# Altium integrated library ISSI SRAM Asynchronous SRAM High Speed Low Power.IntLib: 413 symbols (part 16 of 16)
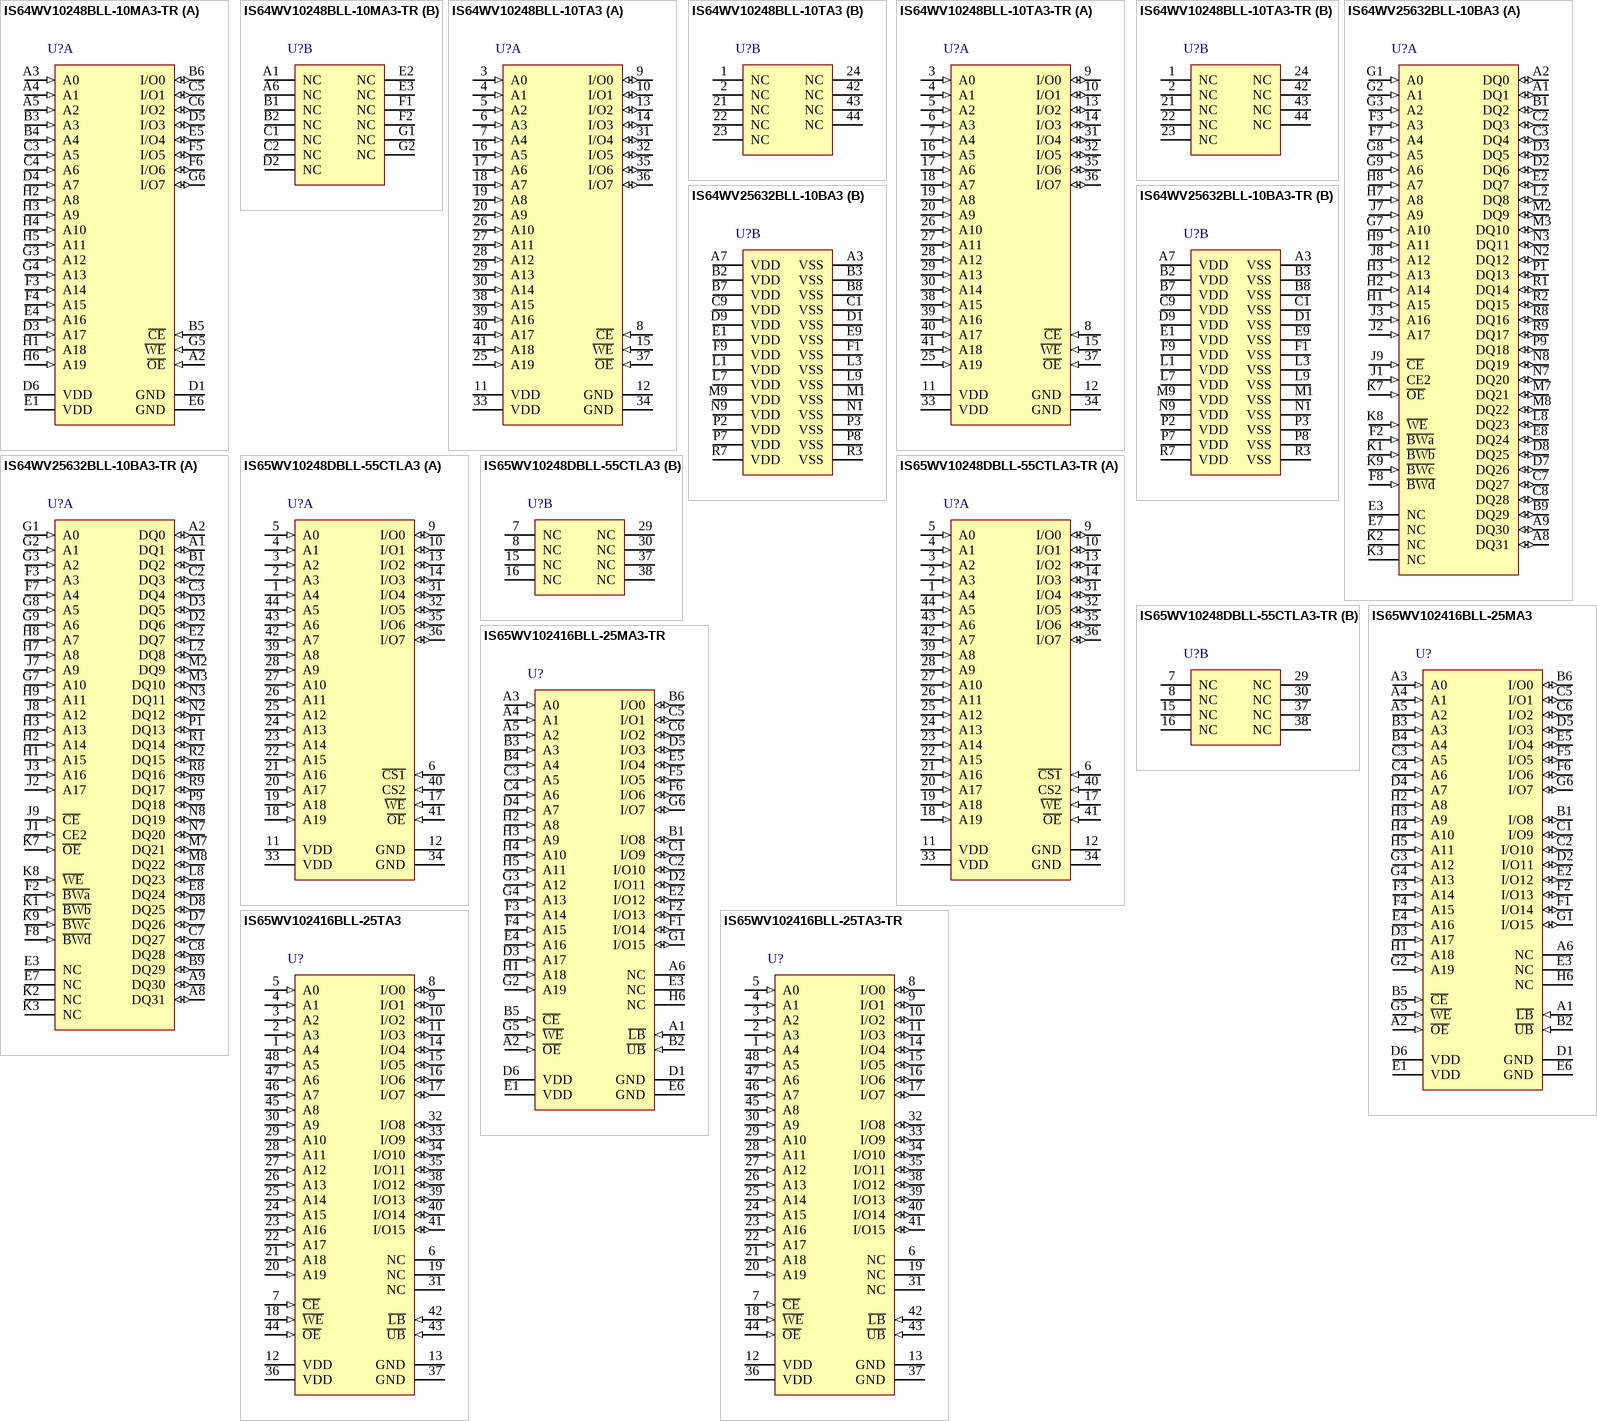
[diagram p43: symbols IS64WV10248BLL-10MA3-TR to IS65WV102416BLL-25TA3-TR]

## IS65WV10248DBLL-55CTLA3
designator U?
8 M Low Voltage, Ultra Low Power CMOS SRAM, 1 M x 8, -40 to 125 degC, 44-Pin SOP (TSOP-2-44), Pb-Free; Manufacturer: Integrated Silicon Solution Inc (ISSI); PartNumber: IS65WV10248DBLL-55CTLA3; Density: 8M; Organization: 1M x 8; Packing: Tray / Tube; Speed (ns): 55
footprint ISSI-TSOP-2-44_N (SOP, 44-Leads, Body 18.5x10.3mm, Pitch 0.8mm, IPC Medium Density)
part A pins: 1 A4 (in) "Address Input", 2 A3 (in) "Address Input", 3 A2 (in) "Address Input", 4 A1 (in) "Address Input", 5 A0 (in) "Address Input", 6 ~{CS1} (in) "Chip Enable 1 Input", 9 I/O0 (io) "Input/Output", 10 I/O1 (io) "Input/Output", 11 VDD (power) "Power", 12 GND (power) "Ground", 13 I/O2 (io) "Input/Output", 14 I/O3 (io) "Input/Output", 17 ~{WE} (in) "Write Enable Input", 18 A19 (in) "Address Input", 19 A18 (in) "Address Input", 20 A17 (in) "Address Input", 21 A16 (in) "Address Input", 22 A15 (in) "Address Input", 23 A14 (in) "Address Input", 24 A13 (in) "Address Input", 25 A12 (in) "Address Input", 26 A11 (in) "Address Input", 27 A10 (in) "Address Input", 28 A9 (in) "Address Input", 31 I/O4 (io) "Input/Output", 32 I/O5 (io) "Input/Output", 33 VDD (power) "Power", 34 GND (power) "Ground", 35 I/O6 (io) "Input/Output", 36 I/O7 (io) "Input/Output", 39 A8 (in) "Address Input", 40 CS2 (in) "Chip Enable 2 Input", 41 ~{OE} (in) "Output Enable Input", 42 A7 (in) "Address Input", 43 A6 (in) "Address Input", 44 A5 (in) "Address Input"
part B pins: 7 NC "No Connection", 8 NC "No Connection", 15 NC "No Connection", 16 NC "No Connection", 29 NC "No Connection", 30 NC "No Connection", 37 NC "No Connection", 38 NC "No Connection"

## IS65WV10248DBLL-55CTLA3-TR
designator U?
8 M Low Voltage, Ultra Low Power CMOS SRAM, 1 M x 8, -40 to 125 degC, 44-Pin SOP (TSOP-2-44), Pb-Free; Manufacturer: Integrated Silicon Solution Inc (ISSI); PartNumber: IS65WV10248DBLL-55CTLA3-TR; Density: 8M; Organization: 1M x 8; Packing: Tape & Reel; Speed (ns): 55
footprint ISSI-TSOP-2-44_N (SOP, 44-Leads, Body 18.5x10.3mm, Pitch 0.8mm, IPC Medium Density)
part A pins: 1 A4 (in) "Address Input", 2 A3 (in) "Address Input", 3 A2 (in) "Address Input", 4 A1 (in) "Address Input", 5 A0 (in) "Address Input", 6 ~{CS1} (in) "Chip Enable 1 Input", 9 I/O0 (io) "Input/Output", 10 I/O1 (io) "Input/Output", 11 VDD (power) "Power", 12 GND (power) "Ground", 13 I/O2 (io) "Input/Output", 14 I/O3 (io) "Input/Output", 17 ~{WE} (in) "Write Enable Input", 18 A19 (in) "Address Input", 19 A18 (in) "Address Input", 20 A17 (in) "Address Input", 21 A16 (in) "Address Input", 22 A15 (in) "Address Input", 23 A14 (in) "Address Input", 24 A13 (in) "Address Input", 25 A12 (in) "Address Input", 26 A11 (in) "Address Input", 27 A10 (in) "Address Input", 28 A9 (in) "Address Input", 31 I/O4 (io) "Input/Output", 32 I/O5 (io) "Input/Output", 33 VDD (power) "Power", 34 GND (power) "Ground", 35 I/O6 (io) "Input/Output", 36 I/O7 (io) "Input/Output", 39 A8 (in) "Address Input", 40 CS2 (in) "Chip Enable 2 Input", 41 ~{OE} (in) "Output Enable Input", 42 A7 (in) "Address Input", 43 A6 (in) "Address Input", 44 A5 (in) "Address Input"
part B pins: 7 NC "No Connection", 8 NC "No Connection", 15 NC "No Connection", 16 NC "No Connection", 29 NC "No Connection", 30 NC "No Connection", 37 NC "No Connection", 38 NC "No Connection"

## IS65WV102416BLL-25MA3
designator U?
16 M High Speed Low Power Asynchronous CMOS SRAM, 1 M x 16, -40 to 125 degC, 48-Pin BGA (TF-BGA-48); Manufacturer: Integrated Silicon Solution Inc (ISSI); PartNumber: IS65WV102416BLL-25MA3; Density: 16M; Organization: 1M x 16; Packing: Tray / Tube; Speed (ns): 25
footprint ISSI-TF-BGA-48-9000x11000DE (BGA, 48-Balls, Body 11x9mm, Pitch 0.75mm)
pins: A1 ~{LB} (in) "Lower-byte Control (I/O0-I/O7)", A2 ~{OE} (in) "Output Enable Input", A3 A0 (in) "Address Input", A4 A1 (in) "Address Input", A5 A2 (in) "Address Input", A6 NC "No Connection", B1 I/O8 (io) "Data Inputs/Output", B2 ~{UB} (in) "Upper-byte Control (I/O8-I/O15)", B3 A3 (in) "Address Input", B4 A4 (in) "Address Input", B5 ~{CE} (in) "Chip Enable Input", B6 I/O0 (io) "Data Inputs/Output", C1 I/O9 (io) "Data Inputs/Output", C2 I/O10 (io) "Data Inputs/Output", C3 A5 (in) "Address Input", C4 A6 (in) "Address Input", C5 I/O1 (io) "Data Inputs/Output", C6 I/O2 (io) "Data Inputs/Output", D1 GND (power) "Ground", D2 I/O11 (io) "Data Inputs/Output", D3 A17 (in) "Address Input", D4 A7 (in) "Address Input", D5 I/O3 (io) "Data Inputs/Output", D6 VDD (power) "Power", E1 VDD (power) "Power", E2 I/O12 (io) "Data Inputs/Output", E3 NC "No Connection", E4 A16 (in) "Address Input", E5 I/O4 (io) "Data Inputs/Output", E6 GND (power) "Ground", F1 I/O14 (io) "Data Inputs/Output", F2 I/O13 (io) "Data Inputs/Output", F3 A14 (in) "Address Input", F4 A15 (in) "Address Input", F5 I/O5 (io) "Data Inputs/Output", F6 I/O6 (io) "Data Inputs/Output", G1 I/O15 (io) "Data Inputs/Output", G2 A19 (in) "Address Input", G3 A12 (in) "Address Input", G4 A13 (in) "Address Input", G5 ~{WE} (in) "Write Enable Input", G6 I/O7 (io) "Data Inputs/Output", H1 A18 (in) "Address Input", H2 A8 (in) "Address Input", H3 A9 (in) "Address Input", H4 A10 (in) "Address Input", H5 A11 (in) "Address Input", H6 NC "No Connection"

## IS65WV102416BLL-25MA3-TR
designator U?
16 M High Speed Low Power Asynchronous CMOS SRAM, 1 M x 16, -40 to 125 degC, 48-Pin BGA (TF-BGA-48); Manufacturer: Integrated Silicon Solution Inc (ISSI); PartNumber: IS65WV102416BLL-25MA3-TR; Density: 16M; Organization: 1M x 16; Packing: Tape & Reel; Speed (ns): 25
footprint ISSI-TF-BGA-48-9000x11000DE (BGA, 48-Balls, Body 11x9mm, Pitch 0.75mm)
pins: A1 ~{LB} (in) "Lower-byte Control (I/O0-I/O7)", A2 ~{OE} (in) "Output Enable Input", A3 A0 (in) "Address Input", A4 A1 (in) "Address Input", A5 A2 (in) "Address Input", A6 NC "No Connection", B1 I/O8 (io) "Data Inputs/Output", B2 ~{UB} (in) "Upper-byte Control (I/O8-I/O15)", B3 A3 (in) "Address Input", B4 A4 (in) "Address Input", B5 ~{CE} (in) "Chip Enable Input", B6 I/O0 (io) "Data Inputs/Output", C1 I/O9 (io) "Data Inputs/Output", C2 I/O10 (io) "Data Inputs/Output", C3 A5 (in) "Address Input", C4 A6 (in) "Address Input", C5 I/O1 (io) "Data Inputs/Output", C6 I/O2 (io) "Data Inputs/Output", D1 GND (power) "Ground", D2 I/O11 (io) "Data Inputs/Output", D3 A17 (in) "Address Input", D4 A7 (in) "Address Input", D5 I/O3 (io) "Data Inputs/Output", D6 VDD (power) "Power", E1 VDD (power) "Power", E2 I/O12 (io) "Data Inputs/Output", E3 NC "No Connection", E4 A16 (in) "Address Input", E5 I/O4 (io) "Data Inputs/Output", E6 GND (power) "Ground", F1 I/O14 (io) "Data Inputs/Output", F2 I/O13 (io) "Data Inputs/Output", F3 A14 (in) "Address Input", F4 A15 (in) "Address Input", F5 I/O5 (io) "Data Inputs/Output", F6 I/O6 (io) "Data Inputs/Output", G1 I/O15 (io) "Data Inputs/Output", G2 A19 (in) "Address Input", G3 A12 (in) "Address Input", G4 A13 (in) "Address Input", G5 ~{WE} (in) "Write Enable Input", G6 I/O7 (io) "Data Inputs/Output", H1 A18 (in) "Address Input", H2 A8 (in) "Address Input", H3 A9 (in) "Address Input", H4 A10 (in) "Address Input", H5 A11 (in) "Address Input", H6 NC "No Connection"

## IS65WV102416BLL-25TA3
designator U?
16 M High Speed Low Power Asynchronous CMOS SRAM, 1 M x 16, -40 to 125 degC, 48-Pin SOP (TSOP-1-48); Manufacturer: Integrated Silicon Solution Inc (ISSI); PartNumber: IS65WV102416BLL-25TA3; Density: 16M; Organization: 1M x 16; Packing: Tray / Tube; Speed (ns): 25
footprint ISSI-TSOP-1-48-12000X20000DE_N (SOP, 48-Leads, Body 18.6x12.2mm, Pitch 0.5mm, IPC Medium Density)
pins: 1 A4 (in) "Address Input", 2 A3 (in) "Address Input", 3 A2 (in) "Address Input", 4 A1 (in) "Address Input", 5 A0 (in) "Address Input", 6 NC "No Connection", 7 ~{CE} (in) "Chip Enable Input", 8 I/O0 (io) "Data Input/Output", 9 I/O1 (io) "Data Input/Output", 10 I/O2 (io) "Data Input/Output", 11 I/O3 (io) "Data Input/Output", 12 VDD (power) "Power", 13 GND (power) "Ground", 14 I/O4 (io) "Data Input/Output", 15 I/O5 (io) "Data Input/Output", 16 I/O6 (io) "Data Input/Output", 17 I/O7 (io) "Data Input/Output", 18 ~{WE} (in) "Write Enable Input", 19 NC "No Connection", 20 A19 (in) "Address Input", 21 A18 (in) "Address Input", 22 A17 (in) "Address Input", 23 A16 (in) "Address Input", 24 A15 (in) "Address Input", 25 A14 (in) "Address Input", 26 A13 (in) "Address Input", 27 A12 (in) "Address Input", 28 A11 (in) "Address Input", 29 A10 (in) "Address Input", 30 A9 (in) "Address Input", 31 NC "No Connection", 32 I/O8 (io) "Data Input/Output", 33 I/O9 (io) "Data Input/Output", 34 I/O10 (io) "Data Input/Output", 35 I/O11 (io) "Data Input/Output", 36 VDD (power) "Power", 37 GND (power) "Ground", 38 I/O12 (io) "Data Input/Output", 39 I/O13 (io) "Data Input/Output", 40 I/O14 (io) "Data Input/Output", 41 I/O15 (io) "Data Input/Output", 42 ~{LB} (in) "Lower-byte Control (I/O0-I/O7)", 43 ~{UB} (in) "Upper-byte Control (I/O8-I/O15)", 44 ~{OE} (in) "Output Enable Input", 45 A8 (in) "Address Input", 46 A7 (in) "Address Input", 47 A6 (in) "Address Input", 48 A5 (in) "Address Input"

## IS65WV102416BLL-25TA3-TR
designator U?
16 M High Speed Low Power Asynchronous CMOS SRAM, 1 M x 16, -40 to 125 degC, 48-Pin SOP (TSOP-1-48); Manufacturer: Integrated Silicon Solution Inc (ISSI); PartNumber: IS65WV102416BLL-25TA3-TR; Density: 16M; Organization: 1M x 16; Packing: Tape & Reel; Speed (ns): 25
footprint ISSI-TSOP-1-48-12000X20000DE_N (SOP, 48-Leads, Body 18.6x12.2mm, Pitch 0.5mm, IPC Medium Density)
pins: 1 A4 (in) "Address Input", 2 A3 (in) "Address Input", 3 A2 (in) "Address Input", 4 A1 (in) "Address Input", 5 A0 (in) "Address Input", 6 NC "No Connection", 7 ~{CE} (in) "Chip Enable Input", 8 I/O0 (io) "Data Input/Output", 9 I/O1 (io) "Data Input/Output", 10 I/O2 (io) "Data Input/Output", 11 I/O3 (io) "Data Input/Output", 12 VDD (power) "Power", 13 GND (power) "Ground", 14 I/O4 (io) "Data Input/Output", 15 I/O5 (io) "Data Input/Output", 16 I/O6 (io) "Data Input/Output", 17 I/O7 (io) "Data Input/Output", 18 ~{WE} (in) "Write Enable Input", 19 NC "No Connection", 20 A19 (in) "Address Input", 21 A18 (in) "Address Input", 22 A17 (in) "Address Input", 23 A16 (in) "Address Input", 24 A15 (in) "Address Input", 25 A14 (in) "Address Input", 26 A13 (in) "Address Input", 27 A12 (in) "Address Input", 28 A11 (in) "Address Input", 29 A10 (in) "Address Input", 30 A9 (in) "Address Input", 31 NC "No Connection", 32 I/O8 (io) "Data Input/Output", 33 I/O9 (io) "Data Input/Output", 34 I/O10 (io) "Data Input/Output", 35 I/O11 (io) "Data Input/Output", 36 VDD (power) "Power", 37 GND (power) "Ground", 38 I/O12 (io) "Data Input/Output", 39 I/O13 (io) "Data Input/Output", 40 I/O14 (io) "Data Input/Output", 41 I/O15 (io) "Data Input/Output", 42 ~{LB} (in) "Lower-byte Control (I/O0-I/O7)", 43 ~{UB} (in) "Upper-byte Control (I/O8-I/O15)", 44 ~{OE} (in) "Output Enable Input", 45 A8 (in) "Address Input", 46 A7 (in) "Address Input", 47 A6 (in) "Address Input", 48 A5 (in) "Address Input"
